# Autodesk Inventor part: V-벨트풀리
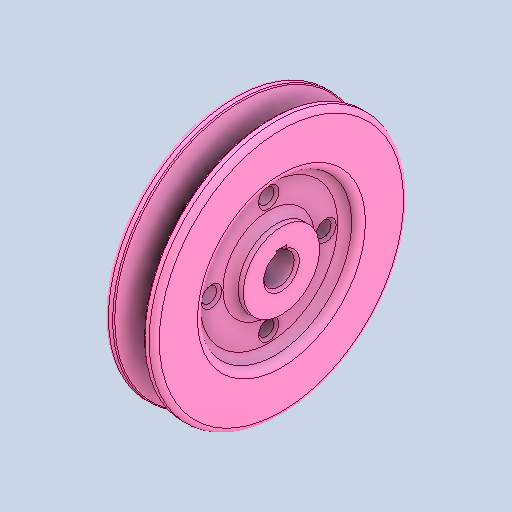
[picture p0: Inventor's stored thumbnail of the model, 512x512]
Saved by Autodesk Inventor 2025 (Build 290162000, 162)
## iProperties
Created: 2024-07
Part Number: V-벨트풀리
Material: 강철, 연강
Document SubType Name: Modeling
Designer: samsung
Density: 7.86 g/cm^3
Appearance: 기본값
Author: jhkim
Sending System: Autodesk Inventor 2025
Preprocessor: ST-DEVELOPER v20
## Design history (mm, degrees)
feature "솔리드1"
node "솔리드2"
